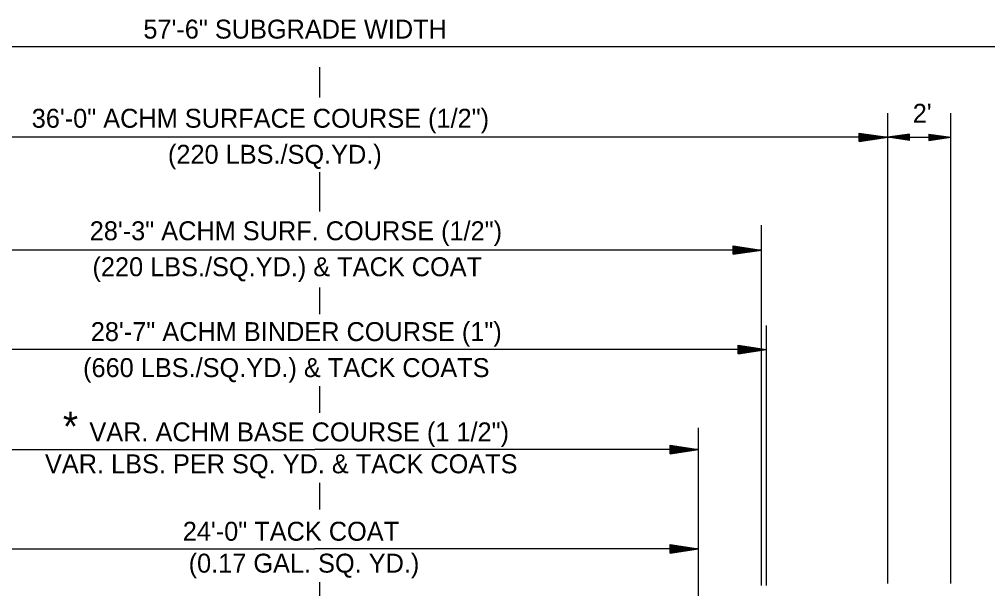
# Model space of a CAD drawing. Extents: x 634177 to 635904, y 289936 to 290970.
# Drawn here: x 635841.15 to 635871.85, y 290618.08 to 290636.11 of the extents above; entities that cross this region are included whole.
import ezdxf

# ---------------------------------------------------------------- set-up
doc = ezdxf.new("R2010")
doc.units = 0
doc.layers.add('Default', color=7, linetype='Continuous')

msp = doc.modelspace()

# ---------------------------------------------------------------- linework, layer by layer
at = {"layer": 'Default'}
for p, q in [((635878.958, 290635.246), (635822.398, 290635.246)), ((635850.678, 290633.633), (635850.678, 290634.593)), ((635868.678, 290618.24), (635868.678, 290633.142)), ((635870.678, 290618.24), (635870.678, 290633.142)), ((635868.678, 290632.376), (635832.678, 290632.376)), ((635867.778, 290632.511), (635868.678, 290632.376)), ((635867.778, 290632.241), (635867.778, 290632.511)), ((635867.778, 290632.489), (635868.528, 290632.376)), ((635867.778, 290632.466), (635868.373, 290632.376)), ((635867.778, 290632.443), (635868.223, 290632.376)), ((635867.778, 290632.421), (635868.07, 290632.376)), ((635867.778, 290632.398), (635867.92, 290632.376)), ((635867.778, 290632.241), (635868.678, 290632.376)), ((635867.778, 290632.333), (635868.07, 290632.376)), ((635867.778, 290632.286), (635868.373, 290632.376)), ((635867.778, 290632.264), (635868.528, 290632.376)), ((635867.778, 290632.31), (635868.223, 290632.376)), ((635867.778, 290632.355), (635867.92, 290632.376)), ((635869.368, 290632.48), (635868.678, 290632.376)), ((635868.678, 290632.376), (635870.678, 290632.376)), ((635869.368, 290632.273), (635868.678, 290632.376)), ((635869.368, 290632.463), (635868.793, 290632.376)), ((635869.368, 290632.29), (635868.793, 290632.376)), ((635869.368, 290632.445), (635868.912, 290632.376)), ((635869.368, 290632.308), (635868.912, 290632.376)), ((635869.368, 290632.428), (635869.027, 290632.376)), ((635869.368, 290632.325), (635869.027, 290632.376)), ((635869.368, 290632.41), (635869.144, 290632.376)), ((635869.368, 290632.343), (635869.144, 290632.376)), ((635869.368, 290632.393), (635869.259, 290632.376)), ((635869.368, 290632.36), (635869.259, 290632.376)), ((635869.368, 290632.273), (635869.368, 290632.48)), ((635869.988, 290632.48), (635870.678, 290632.376)), ((635869.988, 290632.48), (635869.988, 290632.273)), ((635869.988, 290632.463), (635870.563, 290632.376)), ((635869.988, 290632.445), (635870.444, 290632.376)), ((635869.988, 290632.428), (635870.329, 290632.376)), ((635869.988, 290632.41), (635870.212, 290632.376)), ((635869.988, 290632.393), (635870.097, 290632.376)), ((635869.988, 290632.273), (635870.678, 290632.376)), ((635869.988, 290632.343), (635870.212, 290632.376)), ((635869.988, 290632.308), (635870.444, 290632.376)), ((635869.988, 290632.29), (635870.563, 290632.376)), ((635869.988, 290632.325), (635870.329, 290632.376)), ((635869.988, 290632.36), (635870.097, 290632.376)), ((635850.678, 290630.031), (635850.678, 290631.276)), ((635864.678, 290618.183), (635864.678, 290629.591)), ((635864.678, 290628.805), (635836.649, 290628.805)), ((635863.778, 290628.94), (635864.678, 290628.805)), ((635863.778, 290628.67), (635863.778, 290628.94)), ((635863.778, 290628.918), (635864.528, 290628.805)), ((635863.778, 290628.895), (635864.373, 290628.805)), ((635863.778, 290628.872), (635864.223, 290628.805)), ((635863.778, 290628.849), (635864.07, 290628.805)), ((635863.778, 290628.827), (635863.92, 290628.805)), ((635863.778, 290628.67), (635864.678, 290628.805)), ((635863.778, 290628.762), (635864.07, 290628.805)), ((635863.778, 290628.715), (635864.373, 290628.805)), ((635863.778, 290628.693), (635864.528, 290628.805)), ((635863.778, 290628.739), (635864.223, 290628.805)), ((635863.778, 290628.784), (635863.92, 290628.805)), ((635850.678, 290626.774), (635850.678, 290627.618)), ((635864.839, 290618.183), (635864.839, 290626.419)), ((635864.678, 290625.658), (635836.517, 290625.658)), ((635863.939, 290625.793), (635864.839, 290625.658)), ((635863.939, 290625.523), (635863.939, 290625.793)), ((635863.939, 290625.771), (635864.688, 290625.658)), ((635863.939, 290625.748), (635864.534, 290625.658)), ((635863.939, 290625.725), (635864.384, 290625.658)), ((635863.939, 290625.702), (635864.231, 290625.658)), ((635863.939, 290625.68), (635864.081, 290625.658)), ((635863.939, 290625.523), (635864.839, 290625.658)), ((635863.939, 290625.615), (635864.231, 290625.658)), ((635863.939, 290625.568), (635864.534, 290625.658)), ((635863.939, 290625.546), (635864.688, 290625.658)), ((635863.939, 290625.592), (635864.384, 290625.658)), ((635863.939, 290625.637), (635864.081, 290625.658)), ((635850.678, 290623.65), (635850.678, 290624.494)), ((635862.678, 290612.837), (635862.678, 290623.179)), ((635861.778, 290622.625), (635862.678, 290622.49)), ((635861.778, 290622.355), (635861.778, 290622.625)), ((635861.778, 290622.603), (635862.528, 290622.49)), ((635861.778, 290622.58), (635862.373, 290622.49)), ((635861.778, 290622.557), (635862.223, 290622.49)), ((635838.678, 290622.49), (635850.518, 290622.49)), ((635862.678, 290622.49), (635850.518, 290622.49)), ((635861.778, 290622.535), (635862.07, 290622.49)), ((635861.778, 290622.512), (635861.92, 290622.49)), ((635861.778, 290622.355), (635862.678, 290622.49)), ((635861.778, 290622.447), (635862.07, 290622.49)), ((635861.778, 290622.4), (635862.373, 290622.49)), ((635861.778, 290622.378), (635862.528, 290622.49)), ((635861.778, 290622.424), (635862.223, 290622.49)), ((635861.778, 290622.469), (635861.92, 290622.49)), ((635850.678, 290620.59), (635850.678, 290621.434)), ((635838.678, 290619.343), (635850.518, 290619.343)), ((635862.678, 290619.343), (635850.518, 290619.343)), ((635861.778, 290619.478), (635862.678, 290619.343)), ((635861.778, 290619.208), (635861.778, 290619.478)), ((635861.778, 290619.456), (635862.528, 290619.343)), ((635861.778, 290619.433), (635862.373, 290619.343)), ((635861.778, 290619.41), (635862.223, 290619.343)), ((635861.778, 290619.388), (635862.07, 290619.343)), ((635861.778, 290619.365), (635861.92, 290619.343)), ((635861.778, 290619.208), (635862.678, 290619.343)), ((635861.778, 290619.3), (635862.07, 290619.343)), ((635861.778, 290619.253), (635862.373, 290619.343)), ((635861.778, 290619.231), (635862.528, 290619.343)), ((635861.778, 290619.277), (635862.223, 290619.343)), ((635861.778, 290619.322), (635861.92, 290619.343)), ((635850.678, 290612.314), (635850.678, 290618.287))]:
    msp.add_line(p, q, dxfattribs=at)

# ---------------------------------------------------------------- texts
for s, height, p in [('57\'-6" SUBGRADE WIDTH', 0.6, (635845.082, 290635.503)), ('36\'-0" ACHM SURFACE COURSE (1/2")', 0.6, (635841.543, 290632.679)), ("2'", 0.6, (635869.472, 290632.837)), ('(220 LBS./SQ.YD.)', 0.6, (635845.861, 290631.539)), ('28\'-3" ACHM SURF. COURSE (1/2")', 0.6, (635843.382, 290629.116)), ('(220 LBS./SQ.YD.) & TACK COAT', 0.6, (635843.469, 290627.976)), ('28\'-7" ACHM BINDER COURSE (1")', 0.6, (635843.416, 290625.922)), ('(660 LBS./SQ.YD.) & TACK COATS', 0.6, (635843.171, 290624.782)), ('*', 0.931, (635842.529, 290622.755)), ('VAR. ACHM BASE COURSE (1 1/2")', 0.6, (635843.371, 290622.746)), ('VAR. LBS. PER SQ. YD. & TACK COATS', 0.6, (635841.963, 290621.735)), ('24\'-0" TACK COAT', 0.6, (635846.331, 290619.599)), ('(0.17 GAL. SQ. YD.)', 0.6, (635846.518, 290618.588))]:
    msp.add_text(s, height=height, dxfattribs=at).set_placement(p)

doc.saveas('drawing.dxf')
